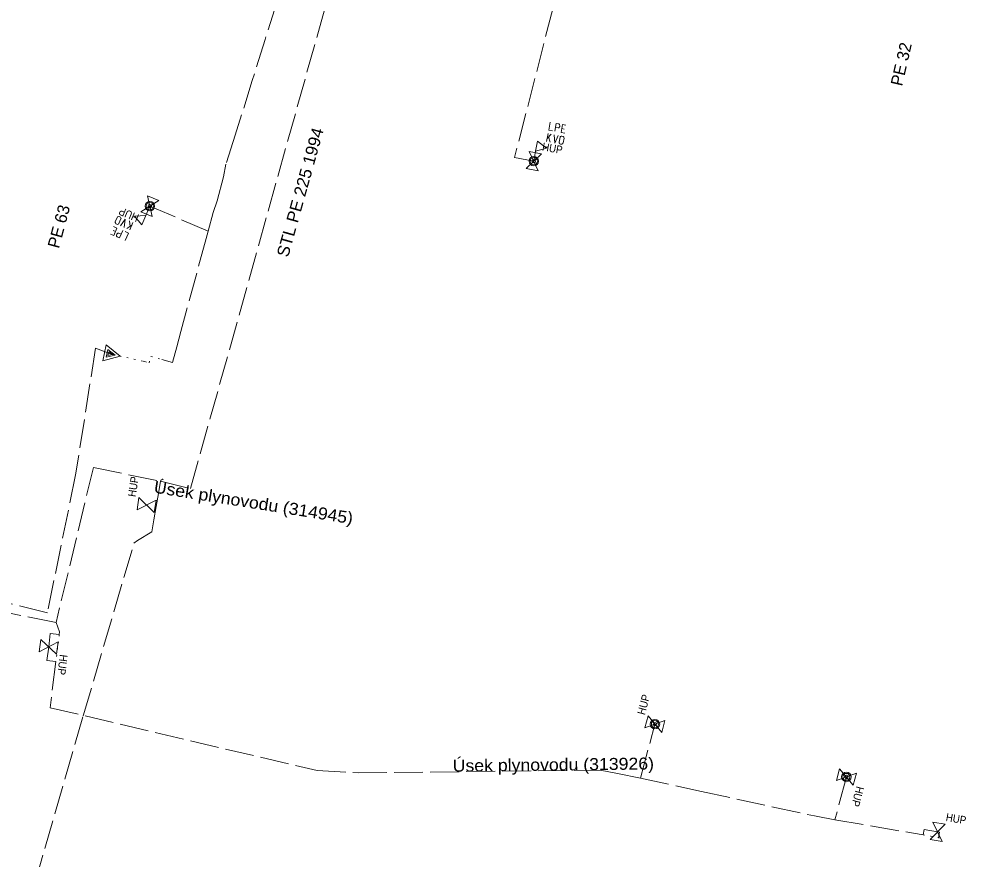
# Model space of a CAD drawing. Extents: x -688140 to -687678, y -1056859 to -1056384.
# Drawn here: x -688074.2 to -688015.1, y -1056699.8 to -1056647.4 of the extents above; entities that cross this region are included whole.
import ezdxf
from ezdxf.enums import TextEntityAlignment as Align

# ---------------------------------------------------------------- set-up
doc = ezdxf.new("R2010")
doc.units = 0
doc.header["$LTSCALE"] = 0.3
doc.linetypes.add('DOTTED', pattern=[1.5, 0.3, -1.2])
doc.linetypes.add('LONG_DASHED', pattern=[7.5, 6, -1.5])
for name, color, linetype, lineweight in [('12', 7, 'Continuous', 13), ('13', 7, 'Continuous', 13), ('35', 7, 'LONG_DASHED', 13), ('36', 7, 'DOTTED', 13), ('40', 7, 'LONG_DASHED', 13), ('41', 7, 'DOTTED', 13), ('50', 7, 'LONG_DASHED', 13)]:
    doc.layers.add(name, color=color, linetype=linetype, lineweight=lineweight)
doc.layers.add('15', color=7, linetype='Continuous')

msp = doc.modelspace()

# ---------------------------------------------------------------- linework, layer by layer
at = {"layer": '12'}
for p, q in [((-688065.481, -1056658.721), (-688066.189, -1056658.417)), ((-688065.911, -1056659.723), (-688066.189, -1056658.417)), ((-688066.619, -1056659.419), (-688065.481, -1056658.721)), ((-688066.05, -1056659.07), (-688066.298, -1056659.649)), ((-688065.911, -1056659.723), (-688066.619, -1056659.419)), ((-688068.214, -1056660.057), (-688068.092, -1056659.772)), ((-688067.862, -1056659.871), (-688067.984, -1056660.156)), ((-688067.181, -1056660.261), (-688067.486, -1056660.467)), ((-688067.279, -1056660.338), (-688067.317, -1056659.996)), ((-688067.303, -1056660.546), (-688067.106, -1056660.086)), ((-688068.348, -1056660.598), (-688068.201, -1056660.661)), ((-688067.993, -1056660.761), (-688067.846, -1056660.824))]:
    msp.add_line(p, q, dxfattribs=at)
for points in [[(-688067.862, -1056659.871), (-688067.846, -1056659.834), (-688067.857, -1056659.808), (-688067.882, -1056659.765), (-688067.915, -1056659.74), (-688067.961, -1056659.72), (-688067.988, -1056659.708), (-688068.041, -1056659.729), (-688068.067, -1056659.74), (-688068.092, -1056659.772)], [(-688067.984, -1056660.156), (-688067.996, -1056660.183), (-688068.026, -1056660.203), (-688068.075, -1056660.215), (-688068.112, -1056660.199), (-688068.157, -1056660.18), (-688068.185, -1056660.168), (-688068.206, -1056660.115), (-688068.217, -1056660.089), (-688068.214, -1056660.057)], [(-688067.652, -1056660.396), (-688067.584, -1056659.881), (-688067.891, -1056660.294)], [(-688068.505, -1056660.814), (-688068.303, -1056660.9), (-688068.106, -1056660.441), (-688068.327, -1056660.346)], [(-688068.092, -1056660.991), (-688068.13, -1056660.953), (-688068.135, -1056660.864), (-688068.119, -1056660.827), (-688068.047, -1056660.76), (-688067.993, -1056660.761)], [(-688067.748, -1056660.594), (-688067.945, -1056661.054), (-688068.092, -1056660.991)], [(-688067.586, -1056661.208), (-688067.389, -1056660.748), (-688067.601, -1056660.657)]]:
    msp.add_lwpolyline(points, dxfattribs=at)
for points in [[(-688066.298, -1056659.649), (-688067.003, -1056659.695), (-688066.55, -1056660.237)], [(-688068.996, -1056668.72), (-688067.898, -1056668.441), (-688068.783, -1056667.733)], [(-688068.776, -1056668.506), (-688068.225, -1056668.37), (-688068.671, -1056668.018)], [(-688068.666, -1056668.397), (-688068.386, -1056668.335), (-688068.615, -1056668.163)]]:
    msp.add_lwpolyline(points, close=True, dxfattribs=at)
for radius in [0.297, 0.223, 0.223, 0.112]:
    msp.add_circle((-688066.05, -1056659.07), radius, dxfattribs=at)
at = {"layer": '13'}
for p, q in [((-688040.55, -1056654.18), (-688040.707, -1056654.151)), ((-688040.168, -1056654.26), (-688040.326, -1056654.231)), ((-688041.176, -1056654.543), (-688041.266, -1056655.035)), ((-688041.232, -1056654.848), (-688040.979, -1056654.579)), ((-688041.153, -1056654.751), (-688041.04, -1056655.076)), ((-688040.481, -1056655.077), (-688040.425, -1056654.772)), ((-688040.179, -1056654.817), (-688040.235, -1056655.122)), ((-688041.593, -1056655.793), (-688042.547, -1056656.727)), ((-688042.35, -1056655.655), (-688041.79, -1056656.865)), ((-688042.35, -1056655.655), (-688041.593, -1056655.793)), ((-688042.07, -1056656.26), (-688041.956, -1056655.64)), ((-688042.547, -1056656.727), (-688041.79, -1056656.865)), ((-688066.849, -1056678.026), (-688066.73, -1056677.265)), ((-688066.849, -1056678.026), (-688065.653, -1056677.432)), ((-688066.73, -1056677.265), (-688065.772, -1056678.193)), ((-688065.772, -1056678.193), (-688065.653, -1056677.432)), ((-688072.861, -1056686.142), (-688072.958, -1056686.906)), ((-688071.78, -1056686.278), (-688072.958, -1056686.906)), ((-688071.877, -1056687.042), (-688072.861, -1056686.142)), ((-688071.78, -1056686.278), (-688071.877, -1056687.042)), ((-688035.128, -1056691.653), (-688034.929, -1056690.909)), ((-688034.929, -1056690.909), (-688034.075, -1056691.935)), ((-688035.128, -1056691.653), (-688033.876, -1056691.191)), ((-688034.075, -1056691.935), (-688033.876, -1056691.191)), ((-688022.972, -1056694.203), (-688023.171, -1056694.947)), ((-688021.919, -1056694.485), (-688023.171, -1056694.947)), ((-688022.118, -1056695.229), (-688022.972, -1056694.203)), ((-688021.919, -1056694.485), (-688022.118, -1056695.229)), ((-688017.136, -1056697.539), (-688016.562, -1056698.743)), ((-688017.136, -1056697.539), (-688016.377, -1056697.669)), ((-688016.377, -1056697.669), (-688017.321, -1056698.613)), ((-688017.321, -1056698.613), (-688016.562, -1056698.743))]:
    msp.add_line(p, q, dxfattribs=at)
for points in [[(-688041.046, -1056653.835), (-688041.136, -1056654.327), (-688040.91, -1056654.368)], [(-688040.752, -1056654.397), (-688040.662, -1056653.905), (-688040.505, -1056653.934)], [(-688040.505, -1056653.934), (-688040.459, -1056653.963), (-688040.434, -1056654.049), (-688040.442, -1056654.088), (-688040.497, -1056654.169), (-688040.55, -1056654.18)], [(-688040.062, -1056654.015), (-688040.279, -1056653.976), (-688040.369, -1056654.467), (-688040.133, -1056654.511)], [(-688040.802, -1056654.612), (-688040.754, -1056655.129), (-688040.546, -1056654.658)], [(-688040.425, -1056654.772), (-688040.419, -1056654.743), (-688040.394, -1056654.717), (-688040.35, -1056654.695), (-688040.31, -1056654.702), (-688040.261, -1056654.711), (-688040.232, -1056654.716), (-688040.199, -1056654.763), (-688040.183, -1056654.786), (-688040.179, -1056654.817)], [(-688040.481, -1056655.077), (-688040.488, -1056655.117), (-688040.472, -1056655.14), (-688040.438, -1056655.177), (-688040.4, -1056655.194), (-688040.351, -1056655.203), (-688040.322, -1056655.208), (-688040.275, -1056655.176), (-688040.252, -1056655.16), (-688040.235, -1056655.122)]]:
    msp.add_lwpolyline(points, dxfattribs=at)
msp.add_lwpolyline([(-688041.956, -1056655.64), (-688041.279, -1056655.439), (-688041.841, -1056655.011)], close=True, dxfattribs=at)
for centre, radius in [((-688042.07, -1056656.26), 0.297), ((-688042.07, -1056656.26), 0.223), ((-688042.07, -1056656.26), 0.223), ((-688042.07, -1056656.26), 0.112), ((-688034.502, -1056691.422), 0.297), ((-688034.502, -1056691.422), 0.223), ((-688034.502, -1056691.422), 0.223), ((-688034.502, -1056691.422), 0.112), ((-688022.545, -1056694.716), 0.297), ((-688022.545, -1056694.716), 0.223), ((-688022.545, -1056694.716), 0.223), ((-688022.545, -1056694.716), 0.112)]:
    msp.add_circle(centre, radius, dxfattribs=at)
at = {"layer": '35'}
for points in [[(-688056.78, -1056642.05), (-688058.85, -1056648.66), (-688059.65, -1056651.23), (-688060.72, -1056654.63), (-688061.3, -1056656.45), (-688061.44, -1056657.24), (-688061.85, -1056658.73), (-688062.1, -1056659.46), (-688062.41, -1056660.63), (-688062.54, -1056661.08), (-688064.11, -1056666.9), (-688064.37, -1056667.86), (-688064.63, -1056668.83), (-688065.31, -1056668.649)], [(-688068.396, -1056668.333), (-688069.437, -1056667.945), (-688070.688, -1056675.841), (-688072.45, -1056684.47), (-688077.51, -1056683.22), (-688084.482, -1056682.546), (-688090.337, -1056681.98), (-688094.945, -1056681.697), (-688098.905, -1056681.128), (-688110.126, -1056680.1), (-688119.276, -1056679.031), (-688128.89, -1056677.72), (-688121.64, -1056647.72)]]:
    msp.add_lwpolyline(points, dxfattribs=at)
at = {"layer": '36'}
msp.add_lwpolyline([(-688068.396, -1056668.333), (-688066.47, -1056668.75), (-688066.36, -1056668.78), (-688066.09, -1056668.85), (-688065.98, -1056668.46), (-688065.31, -1056668.649)], dxfattribs=at)
at = {"layer": '40'}
msp.add_line((-688069.58, -1056675.4), (-688065.38, -1056676.24), dxfattribs=at)
for points in [[(-688065.38, -1056676.24), (-688063.51, -1056676.71), (-688050.47, -1056630.1)], [(-688069.58, -1056675.4), (-688071.91, -1056685.08), (-688077.6, -1056683.91), (-688087.804, -1056682.95), (-688096.034, -1056682.213), (-688103.554, -1056681.539), (-688106.12, -1056681.32), (-688128.58, -1056678.69), (-688125.804, -1056666.123), (-688122.08, -1056647.65)], [(-688065.38, -1056676.24), (-688065.514, -1056677.008), (-688065.661, -1056677.836)], [(-688119.696, -1056859.349), (-688113.112, -1056836.422), (-688108.744, -1056823.422), (-688107.316, -1056818.815), (-688102.486, -1056802.215), (-688095.777, -1056779.219), (-688089.403, -1056757.389), (-688084.596, -1056740.689), (-688077.601, -1056716.469), (-688070.21, -1056690.89), (-688067.041, -1056680.11), (-688066.815, -1056679.953), (-688065.935, -1056679.399), (-688065.807, -1056678.658), (-688065.661, -1056677.836)], [(-688071.91, -1056685.08), (-688071.686, -1056685.657), (-688071.706, -1056685.819), (-688072.271, -1056685.748), (-688072.369, -1056686.592), (-688072.485, -1056687.442), (-688071.918, -1056687.51), (-688072.28, -1056690.39), (-688055.61, -1056694.32), (-688053.04, -1056694.46), (-688037.92, -1056694.29), (-688036.841, -1056694.505), (-688035.405, -1056694.792), (-688031.59, -1056695.62), (-688024.54, -1056697.15), (-688024.442, -1056697.168), (-688023.26, -1056697.384), (-688017.754, -1056698.34), (-688017.693, -1056697.991), (-688016.849, -1056698.141), (-688016.735, -1056698.16), (-688016.787, -1056698.51), (-688016.72, -1056698.52)]]:
    msp.add_lwpolyline(points, dxfattribs=at)
at = {"layer": '41'}
for points in [[(-688071.706, -1056685.819), (-688071.809, -1056686.638), (-688071.918, -1056687.51)], [(-688017.754, -1056698.34), (-688017.278, -1056698.424), (-688016.787, -1056698.51)]]:
    msp.add_lwpolyline(points, dxfattribs=at)
at = {"layer": '50'}
for p, q in [((-688062.41, -1056660.63), (-688066.05, -1056659.07)), ((-688035.405, -1056694.792), (-688034.502, -1056691.422)), ((-688022.545, -1056694.716), (-688023.26, -1056697.384))]:
    msp.add_line(p, q, dxfattribs=at)
msp.add_lwpolyline([(-688037.39, -1056633.28), (-688039.76, -1056642.38), (-688043.27, -1056656.04), (-688042.07, -1056656.26)], dxfattribs=at)

# ---------------------------------------------------------------- texts
at = {"layer": '12', "width": 0.9}
msp.add_text('HUP', height=0.5, rotation=156.801, dxfattribs=at).set_placement((-688067.265, -1056659.366), align=Align.CENTER)
at = {"layer": '13', "width": 0.9}
for rotation, p in [(349.612, (-688040.951, -1056655.703)), (81.177, (-688066.839, -1056676.625)), (262.804, (-688071.751, -1056687.678)), (75, (-688034.968, -1056690.262)), (255, (-688022.079, -1056695.876)), (350.231, (-688015.736, -1056697.571))]:
    msp.add_text('HUP', height=0.5, rotation=rotation, dxfattribs=at).set_placement(p, align=Align.CENTER)
at = {"layer": '15'}
for s, rotation, p in [('PE 32', 77.049, (-688019.063, -1056651.615)), ('PE 63', 75, (-688071.727, -1056661.754))]:
    msp.add_text(s, height=0.75, rotation=rotation, dxfattribs=at).set_placement(p)
for s, rotation, width, p in [('STL PE 225 1994', 74.37, 1.05, (-688057.418, -1056662.308)), ('Úsek plynovodu (314945)', 350.965, 1.1, (-688065.84, -1056676.96)), ('Úsek plynovodu (313926)', 0.644, 1.1, (-688047.13, -1056694.39))]:
    msp.add_text(s, height=0.75, rotation=rotation, dxfattribs=dict(at, width=width)).set_placement(p)

doc.saveas('drawing.dxf')
